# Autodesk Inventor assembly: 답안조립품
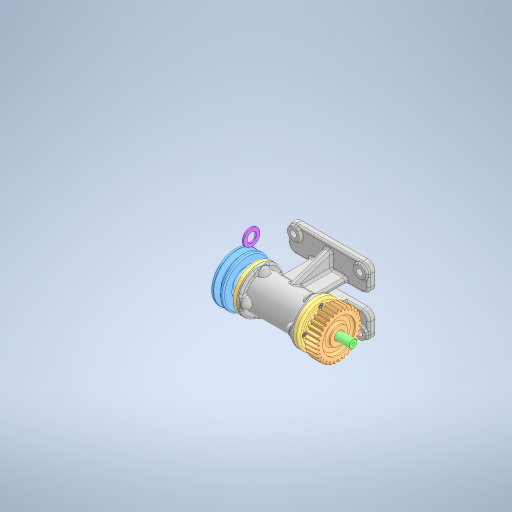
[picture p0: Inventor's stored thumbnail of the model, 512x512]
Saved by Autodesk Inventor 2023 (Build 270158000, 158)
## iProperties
Created: 2026-06
Part Number: 답안조립품
Document SubType Name: Assembly
Designer: home
Author: home
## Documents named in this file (16)
- C:\Users\home\Desktop\760603V1006\답안조립품.iam
- C:\Users\home\Desktop\760603V1006\본체.ipt
- C:\Users\home\Desktop\760403V1014\6각 구멍붙이 볼트 M4x8.ipt
- C:\Users\home\Desktop\760403V1014\6각 너트 M12x1.ipt
- C:\Users\home\Desktop\760403V1014\V 벨트 풀리.ipt
- C:\Users\home\Desktop\760403V1014\깊은 홈 볼 베어링 6904.ipt
- C:\Users\home\Desktop\760403V1014\스퍼 기어.ipt
- C:\Users\home\Desktop\760403V1014\스프링 와셔 M12.ipt
- C:\Users\home\Desktop\760403V1014\오일 실 20 35 8.ipt
- C:\Users\home\Desktop\760403V1014\축.ipt
- C:\Users\home\Desktop\760403V1014\커버.ipt
- C:\Users\home\Desktop\760403V1014\평 와셔 M12.ipt
- C:\Users\home\Desktop\760403V1014\평행 키 4x4x14.ipt
- C:\Users\home\Desktop\760403V1014\커버_MIR.ipt
- C:\Users\home\Desktop\760403V1014\6각 구멍붙이 볼트 M4x8_MIR.ipt
- C:\Users\home\Desktop\760403V1014\오일 실 20 35 8_MIR.ipt
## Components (10 placed, 4 different names)
1. 6각 너트 M12x1:1 — 각도:10
2. V 벨트 풀리:1 — 각도:5
3. 6각 구멍붙이 볼트 M4x8_MIR:1 — 각도:8
4. 6각 구멍붙이 볼트 M4x8_MIR:2 — 각도:6
5. 6각 구멍붙이 볼트 M4x8_MIR:3 — 각도:7
6. 6각 구멍붙이 볼트 M4x8_MIR:4 — 각도:9
7. 6각 구멍붙이 볼트 M4x8:1 — 각도:1
8. 6각 구멍붙이 볼트 M4x8:2
9. 6각 구멍붙이 볼트 M4x8:3
10. 6각 구멍붙이 볼트 M4x8:4
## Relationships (7: Angle 7)
- 각도:1 [Angle]: 6각 구멍붙이 볼트 M4x8:1
- 각도:5 [Angle]: V 벨트 풀리:1
- 각도:6 [Angle]: 6각 구멍붙이 볼트 M4x8_MIR:2
- 각도:7 [Angle]: 6각 구멍붙이 볼트 M4x8_MIR:3
- 각도:8 [Angle]: 6각 구멍붙이 볼트 M4x8_MIR:1
- 각도:9 [Angle]: 6각 구멍붙이 볼트 M4x8_MIR:4
- 각도:10 [Angle]: 6각 너트 M12x1:1
